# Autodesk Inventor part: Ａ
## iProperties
Created: 2007-08
Part Number: Ａ
Document SubType Name: Modeling
Designer: t-ikumi
Density: 1 g/cm^3
Author: t-ikumi
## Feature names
1. 押し出し1 [Extrusion]
2. 押し出し2 [Extrusion]
3. 面取り1 [Chamfer]
4. シェル1
5. 押し出し3 [Extrusion]
6. ミラー1 [Mirror]
7. 押し出し4 [Extrusion]
8. 押し出し5 [Extrusion]
9. 押し出し6 [Extrusion]
10. 放射状パターン1 [Circular Pattern]
11. 面取り2 [Chamfer]
12. 面取り3 [Chamfer]
13. 面取り4 [Chamfer]
14. 面取り5 [Chamfer]
15. 面取り6 [Chamfer]
